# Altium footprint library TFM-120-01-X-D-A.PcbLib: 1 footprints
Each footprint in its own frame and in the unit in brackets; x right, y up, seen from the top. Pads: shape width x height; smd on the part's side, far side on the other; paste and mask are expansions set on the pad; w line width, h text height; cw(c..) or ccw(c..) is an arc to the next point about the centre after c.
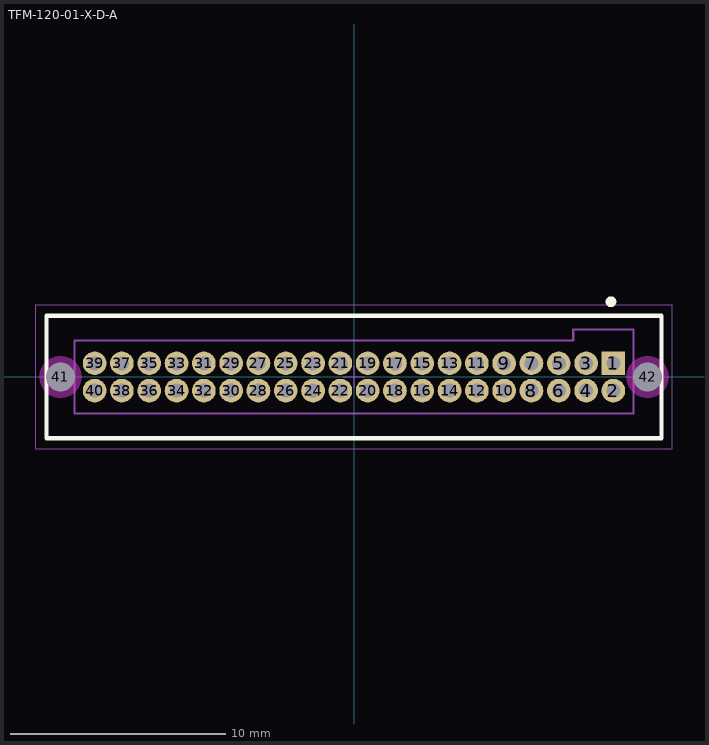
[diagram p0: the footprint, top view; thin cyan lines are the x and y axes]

## TFM-120-01-X-D-A [mm] "1.27mm pitch, 40 pin, terminal strip; PTH"
height 5.59
pads (42):
  rect 1.1x1.1 hole 0.65 unplated mask+0: 1(12.065,0.635)
  round 1.1 hole 0.65 unplated mask+0: 2(12.065,-0.635) 3(10.795,0.635) 4(10.795,-0.635) 5(9.525,0.635) 6(9.525,-0.635) 7(8.255,0.635) 8(8.255,-0.635) 9(6.985,0.635) 10(6.985,-0.635) 11(5.715,0.635) 12(5.715,-0.635) 13(4.445,0.635) 14(4.445,-0.635) 15(3.175,0.635) 16(3.175,-0.635) 17(1.905,0.635) 18(1.905,-0.635) 19(0.635,0.635) 20(0.635,-0.635) 21(-0.635,0.635) 22(-0.635,-0.635) 23(-1.905,0.635) 24(-1.905,-0.635) 25(-3.175,0.635) 26(-3.175,-0.635) 27(-4.445,0.635) 28(-4.445,-0.635) 29(-5.715,0.635) 30(-5.715,-0.635) 31(-6.985,0.635) 32(-6.985,-0.635) 33(-8.255,0.635) 34(-8.255,-0.635) 35(-9.525,0.635) 36(-9.525,-0.635) 37(-10.795,0.635) 38(-10.795,-0.635) 39(-12.065,0.635) 40(-12.065,-0.635)
  round 1 hole 1.35 unplated mask+0: 41(-13.655,0) 42(13.655,0)
Top Overlay:
  circle w0.25: c11.95,3.5 r0.125
  lines w0.2: -14.3,-2.85 -14.3,2.85 14.3,2.85 14.3,-2.85 -14.3,-2.85
Keep-Out Layer:
  pour cut-out: 14.638,0 14.605,0.255 14.507,0.492 14.35,0.695 14.147,0.852 13.91,0.95 13.655,0.983 13.4,0.95 13.163,0.852 12.96,0.695 12.803,0.492 12.705,0.255 12.672,0 12.705,-0.255 12.803,-0.492 12.96,-0.695 13.163,-0.852 13.4,-0.95 13.655,-0.983 13.91,-0.95 14.147,-0.852 14.35,-0.695 14.507,-0.492 14.605,-0.255
  pour cut-out: -12.672,0 -12.705,0.255 -12.803,0.492 -12.96,0.695 -13.163,0.852 -13.4,0.95 -13.655,0.983 -13.91,0.95 -14.147,0.852 -14.35,0.695 -14.507,0.492 -14.605,0.255 -14.638,0 -14.605,-0.255 -14.507,-0.492 -14.35,-0.695 -14.147,-0.852 -13.91,-0.95 -13.655,-0.983 -13.4,-0.95 -13.163,-0.852 -12.96,-0.695 -12.803,-0.492 -12.705,-0.255
Mechanical 12:
  lines w0.001: -14.3,-2.85 -14.3,2.85 14.3,2.85 14.3,-2.85 -14.3,-2.85 ; -13,-1.7 -13,1.702 10.2,1.702 10.2,2.2 13,2.2 13,-1.7 -13,-1.7
Mechanical 13:
  lines w0.1: -14.3,-2.85 -14.3,2.85 14.3,2.85 14.3,-2.85 -14.3,-2.85 ; -13,-1.7 -13,1.702 10.2,1.702 10.2,2.2 13,2.2 13,-1.7 -13,-1.7
  text ".Designator" at 0,-0.127 h1.52
Mechanical 15:
  lines w0.05: -0.5,0 0.5,0 ; 0,-0.5 0,0.5 ; -14.8,-3.35 -14.8,3.35 14.8,3.35 14.8,-3.35 -14.8,-3.35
